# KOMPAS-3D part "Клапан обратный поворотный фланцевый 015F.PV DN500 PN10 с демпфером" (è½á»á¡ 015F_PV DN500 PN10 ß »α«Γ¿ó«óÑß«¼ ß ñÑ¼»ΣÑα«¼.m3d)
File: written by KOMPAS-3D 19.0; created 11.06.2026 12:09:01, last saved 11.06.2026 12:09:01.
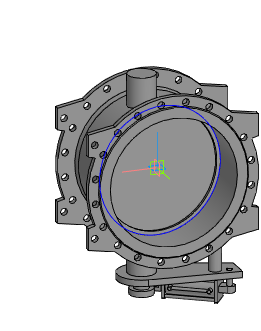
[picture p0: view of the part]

Document properties: Автор: Энергия; Полное имя файла: Z:\3.Личные\kachalov\001_3d для проектировщиков\5.5 Тип 015F.PV Клапан обратный поворотный с двумя эксцентриками\_stp_Клапан 015F.PV DN300-DN1200 с противовесом с демпфером\Клапан 015F_PV DN500 PN10 с противовесом с демпфером.m3d

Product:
- Part/product: Клапан обратный поворотный фланцевый 015F.PV DN500 PN10 с демпфером

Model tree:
1. Операция без истории:1
2. Сплайн:1
     Координата Y = 30; Координата Z = 250; Вес = 1; Координата X = 500; Координата Y = 95.8262; Координата Z = 250; Вес = 0.333333; Координата X = 500; Координата Y = 95.8262; Координата Z = -250; Вес = 0.333333; Координата Y = 30; Координата Z = -250; Вес = 1; Координата X = -500; Координата Y = -35.8262; Координата Z = -250; Вес = 0.333333; Координата X = -500; Координата Y = -35.8262; Координата Z = 250; Вес = 0.333333; Порядок = 4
